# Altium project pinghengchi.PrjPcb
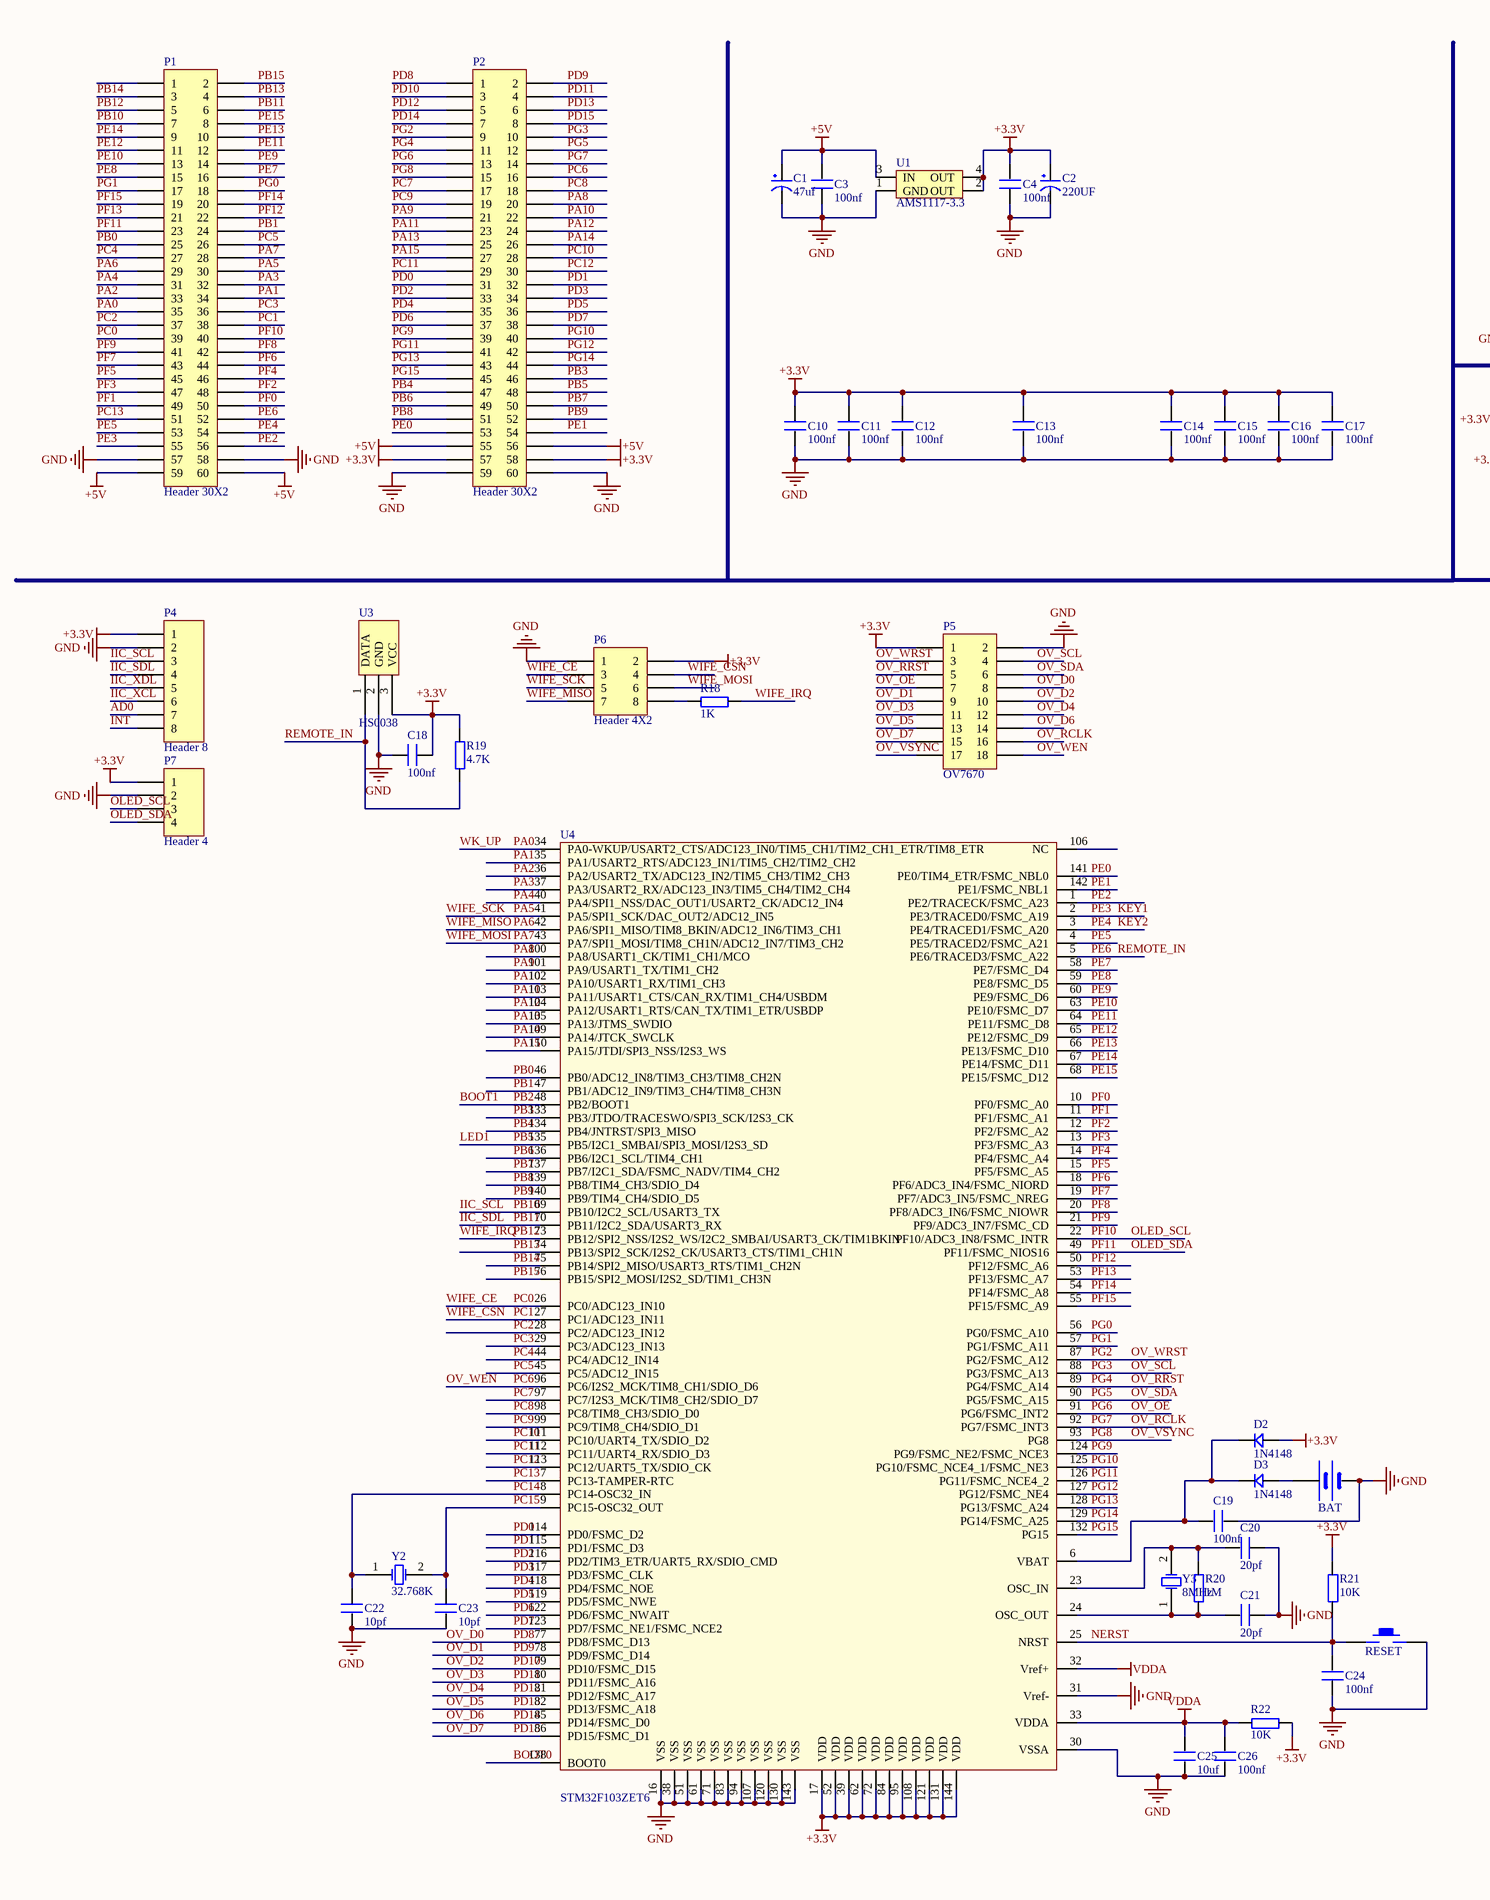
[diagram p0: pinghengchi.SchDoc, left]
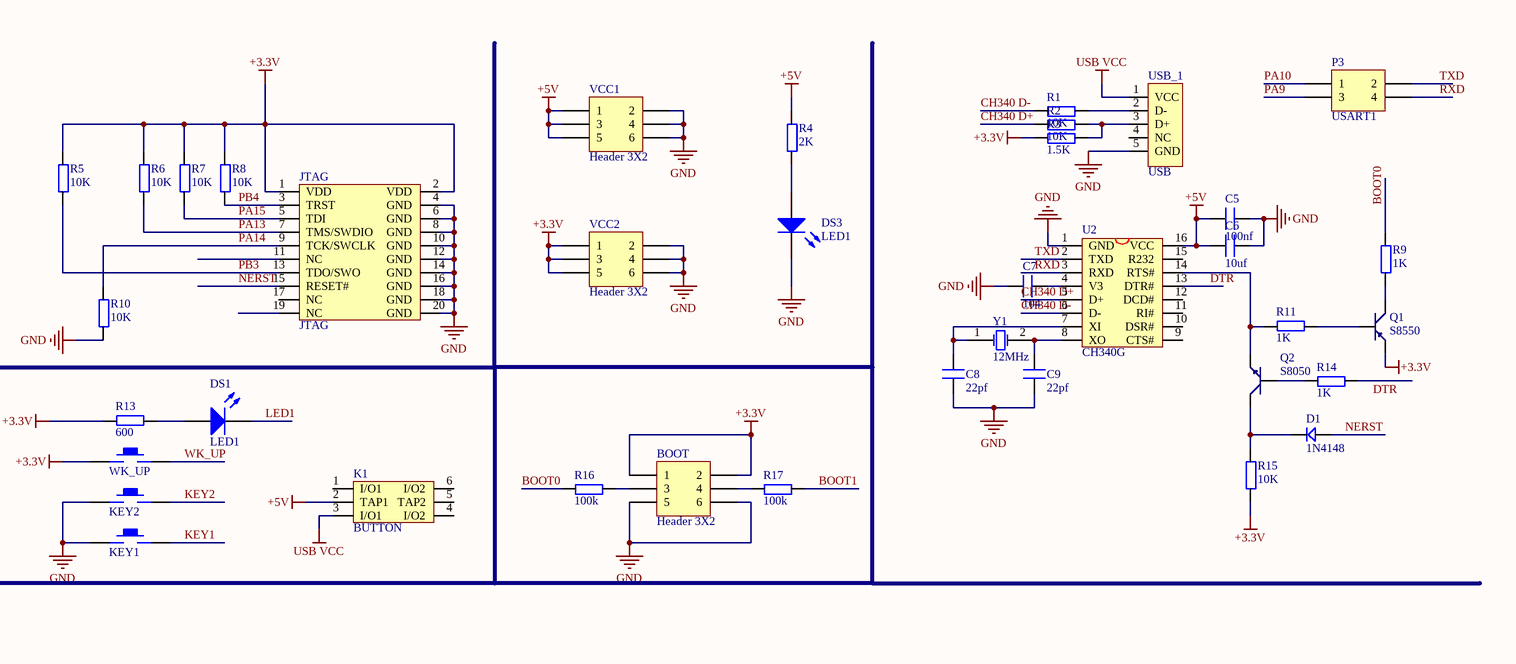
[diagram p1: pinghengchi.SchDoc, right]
1 sheet, 79 parts. Net scope: global (net labels, ports and power ports of the same name join across sheets).
Board file: pinghengchi.PcbDoc

## Sheet pinghengchi.SchDoc
size A2

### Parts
BAT  BATT  [BATM]  (value not drawn)
BOOT  Header 3X2  [HDR2X3]
C1  47uf  [CC6.56.5]
C2  220UF  [CC6.56.5]
C3  100nf  [0603P]
C4  100nf  [0603P]
C5  100nf  [0603P]
C6  10uf  [0603P]
C7  104  [0603P]
C8  22pf  [0603P]
C9  22pf  [0603P]
C10  100nf  [0603P]
C11  100nf  [0603P]
C12  100nf  [0603P]
C13  100nf  [0603P]
C14  100nf  [0603P]
C15  100nf  [0603P]
C16  100nf  [0603P]
C17  100nf  [0603P]
C18  100nf  [0603P]
C19  100nf  [0603P]
C20  20pf  [0603P]
C21  20pf  [0603P]
C22  10pf  [0603P]
C23  10pf  [0603P]
C24  100nf  [0603P]
C25  10uf  [0603P]
C26  100nf  [0603P]
D1  1N4148  [DIODE_SOP]
D2  1N4148  [DIODE_SOP]
D3  1N4148  [DIODE_SOP]
DS1  LED1  [SMDLED]
DS3  LED1  [SMDLED]
JTAG  JTAG  [JTAG_20]
K1  BUTTON  [BTN8.5*8.5]
KEY1  KEY_M  [KEY_M]  (value not drawn)
KEY2  KEY_M  [KEY_M]  (value not drawn)
P1  Header 30X2  [HDR2X30]
P2  Header 30X2  [HDR2X30]
P3  USART1  [HDR2X2]
P4  Header 8  [HDR1X8]
P5  OV7670  [HDR2X9]
P6  Header 4X2  [HDR2X4]
P7  Header 4  [HDR1X4]
Q1  S8550  [SOT-23R]
Q2  S8050  [SOT-23R]
R1  10K  [0603P]
R2  10K  [0603P]
R3  1.5K  [0603P]
R4  2K  [0603P]
R5  10K  [0603P]
R6  10K  [0603P]
R7  10K  [0603P]
R8  10K  [0603P]
R9  1K  [0603P]
R10  10K  [0603P]
R11  1K  [0603P]
R13  600  [0603P]
R14  1K  [0603P]
R15  10K  [0603P]
R16  100k  [0603P]
R17  100k  [0603P]
R18  1K  [0603P]
R19  4.7K  [0603P]
R20  1M  [0603P]
R21  10K  [0603P]
R22  10K  [0603P]
RESET  KEY_M  [KEY_M]  (value not drawn)
U1  AMS1117-3.3  [AMS1117]
U2  CH340G  [SOP16M]
U3  HS0038  [HS0038]
U4  STM32F103ZET6  [LQFP144]
USB_1  USB  [USB/SM0.8-6H5]
VCC1  Header 3X2  [HDR2X3]
VCC2  Header 3X2  [HDR2X3]
WK_UP  KEY_M  [KEY_M]  (value not drawn)
Y1  12MHz  [XTAL_US]
Y2  32.768K  [XTAL_US]
Y3  8MHz  [XTAL_US]

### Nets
+3.3V: BOOT.1 BOOT.2 C2.1(VCC) C4.2 C10.2 C11.2 C12.2 C13.2 C14.2 C15.2 C16.2 C17.2 C18.2 D2.1 JTAG.1(VDD) JTAG.2(VDD) P2.57 P2.58 P4.1 P5.1 P6.2 P7.1 Q1.1(E) R3.1 R5.2 R6.2 R7.2 R8.2 R13.2 R15.1 R19.2 R21.2 R22.2 U1.2(OUT) U1.4(OUT) U3.3(VCC) U4.17(VDD) U4.39(VDD) U4.52(VDD) U4.62(VDD) U4.72(VDD) U4.84(VDD) U4.95(VDD) U4.108(VDD) U4.121(VDD) U4.131(VDD) U4.144(VDD) VCC2.1 VCC2.3 VCC2.5 WK_UP.1
+5V: C1.1(VCC) C3.2 C5.1 C6.1 K1.2(TAP1) P1.59 P1.60 P2.55 P2.56 R4.2 U1.3(IN) U2.16(VCC) VCC1.1 VCC1.3 VCC1.5
GND: BAT.2(GND) BOOT.5 BOOT.6 C1.2(GND) C2.2(GND) C3.1 C4.1 C5.2 C6.2 C7.1 C8.1 C9.1 C10.1 C11.1 C12.1 C13.1 C14.1 C15.1 C16.1 C17.1 C18.1 C19.2 C20.1 C21.1 C22.1 C23.1 C24.1 C25.1 C26.1 DS3.2(K) JTAG.4(GND) JTAG.6(GND) JTAG.8(GND) JTAG.10(GND) JTAG.12(GND) JTAG.14(GND) JTAG.16(GND) JTAG.18(GND) JTAG.20(GND) KEY1.1 KEY2.1 P1.57 P1.58 P2.59 P2.60 P4.2 P5.2 P6.1 P7.2 R10.1 RESET.2 U1.1(GND) U2.1(GND) U3.2(GND) U4.16(VSS) U4.30(VSSA) U4.31(Vref-) U4.38(VSS) U4.51(VSS) U4.61(VSS) U4.71(VSS) U4.83(VSS) U4.94(VSS) U4.107(VSS) U4.120(VSS) U4.130(VSS) U4.143(VSS) USB_1.5(GND) VCC1.2 VCC1.4 VCC1.6 VCC2.2 VCC2.4 VCC2.6
USB VCC: K1.3(I/O1) USB_1.1(VCC)
VDDA: C25.2 C26.2 R22.1 U4.32(Vref+) U4.33(VDDA)
AD0: P4.7
BOOT0: R9.2 R16.1 U4.138(BOOT0)
BOOT1: R17.2 U4.48(PB2/BOOT1)  [also labelled PB2]
CH340 D+: R2.1 U2.5(D+)
CH340 D-: R1.1 U2.6(D-)
DTR: R14.2 U2.13(DTR#)
IIC_SCL: P1.7 P4.3 U4.69(PB10/I2C2_SCL/USART3_TX)  [also labelled PB10]
IIC_SDL: P1.6 P4.4 U4.70(PB11/I2C2_SDA/USART3_RX)  [also labelled PB11]
IIC_XCL: P4.6
IIC_XDL: P4.5
INT: P4.8
KEY1: KEY1.2 P1.55 U4.2(PE3/TRACED0/FSMC_A19)  [also labelled PE3]
KEY2: KEY2.2 P1.54 U4.3(PE4/TRACED1/FSMC_A20)  [also labelled PE4]
LED1: DS1.2(K) P2.48 U4.135(PB5/I2C1_SMBAI/SPI3_MOSI/I2S3_SD)  [also labelled PB5]
NERST: C24.2 D1.1 JTAG.15(RESET#) R21.1 RESET.1 U4.25(NRST)
OLED_SCL: P1.40 P7.3 U4.22(PF10/ADC3_IN8/FSMC_INTR)  [also labelled PF10]
OLED_SDA: P1.23 P7.4 U4.49(PF11/FSMC_NIOS16)  [also labelled PF11]
OV_D0: P2.1 P5.8 U4.77(PD8/FSMC_D13)  [also labelled PD8]
OV_D1: P2.2 P5.9 U4.78(PD9/FSMC_D14)  [also labelled PD9]
OV_D2: P2.3 P5.10 U4.79(PD10/FSMC_D15)  [also labelled PD10]
OV_D3: P2.4 P5.11 U4.80(PD11/FSMC_A16)  [also labelled PD11]
OV_D4: P2.5 P5.12 U4.81(PD12/FSMC_A17)  [also labelled PD12]
OV_D5: P2.6 P5.13 U4.82(PD13/FSMC_A18)  [also labelled PD13]
OV_D6: P2.7 P5.14 U4.85(PD14/FSMC_D0)  [also labelled PD14]
OV_D7: P2.8 P5.15 U4.86(PD15/FSMC_D1)  [also labelled PD15]
OV_OE: P2.13 P5.7 U4.91(PG6/FSMC_INT2)  [also labelled PG6]
OV_RCLK: P2.14 P5.16 U4.92(PG7/FSMC_INT3)  [also labelled PG7]
OV_RRST: P2.11 P5.5 U4.89(PG4/FSMC_A14)  [also labelled PG4]
OV_SCL: P2.10 P5.4 U4.88(PG3/FSMC_A13)  [also labelled PG3]
OV_SDA: P2.12 P5.6 U4.90(PG5/FSMC_A15)  [also labelled PG5]
OV_VSYNC: P2.15 P5.17 U4.93(PG8)  [also labelled PG8]
OV_WEN: P2.16 P5.18 U4.96(PC6/I2S2_MCK/TIM8_CH1/SDIO_D6)  [also labelled PC6]
OV_WRST: P2.9 P5.3 U4.87(PG2/FSMC_A12)  [also labelled PG2]
PA0: P1.35 U4.34(PA0-WKUP/USART2_CTS/ADC123_IN0/TIM5_CH1/TIM2_CH1_ETR/TIM8_ETR) WK_UP.2  [also labelled WK_UP]
PA1: P1.34 U4.35(PA1/USART2_RTS/ADC123_IN1/TIM5_CH2/TIM2_CH2)
PA2: P1.33 U4.36(PA2/USART2_TX/ADC123_IN2/TIM5_CH3/TIM2_CH3)
PA3: P1.32 U4.37(PA3/USART2_RX/ADC123_IN3/TIM5_CH4/TIM2_CH4)
PA4: P1.31 U4.40(PA4/SPI1_NSS/DAC_OUT1/USART2_CK/ADC12_IN4)
PA5: P1.30 P6.5 U4.41(PA5/SPI1_SCK/DAC_OUT2/ADC12_IN5)  [also labelled WIFE_SCK]
PA6: P1.29 P6.7 U4.42(PA6/SPI1_MISO/TIM8_BKIN/ADC12_IN6/TIM3_CH1)  [also labelled WIFE_MISO]
PA7: P1.28 P6.6 U4.43(PA7/SPI1_MOSI/TIM8_CH1N/ADC12_IN7/TIM3_CH2)  [also labelled WIFE_MOSI]
PA8: P2.20 U4.100(PA8/USART1_CK/TIM1_CH1/MCO)
PA9: P2.21 P3.3 U4.101(PA9/USART1_TX/TIM1_CH2)
PA10: P2.22 P3.1 U4.102(PA10/USART1_RX/TIM1_CH3)
PA11: P2.23 U4.103(PA11/USART1_CTS/CAN_RX/TIM1_CH4/USBDM)
PA12: P2.24 U4.104(PA12/USART1_RTS/CAN_TX/TIM1_ETR/USBDP)
PA13: JTAG.7(TMS/SWDIO) P2.25 R6.1 U4.105(PA13/JTMS_SWDIO)
PA14: JTAG.9(TCK/SWCLK) P2.26 R10.2 U4.109(PA14/JTCK_SWCLK)
PA15: JTAG.5(TDI) P2.27 R7.1 U4.110(PA15/JTDI/SPI3_NSS/I2S3_WS)
PB0: P1.25 U4.46(PB0/ADC12_IN8/TIM3_CH3/TIM8_CH2N)
PB1: P1.24 U4.47(PB1/ADC12_IN9/TIM3_CH4/TIM8_CH3N)
PB3: JTAG.13(TDO/SWO) P2.46 R5.1 U4.133(PB3/JTDO/TRACESWO/SPI3_SCK/I2S3_CK)
PB4: JTAG.3(TRST) P2.47 R8.1 U4.134(PB4/JNTRST/SPI3_MISO)
PB6: P2.49 U4.136(PB6/I2C1_SCL/TIM4_CH1)
PB7: P2.50 U4.137(PB7/I2C1_SDA/FSMC_NADV/TIM4_CH2)
PB8: P2.51 U4.139(PB8/TIM4_CH3/SDIO_D4)
PB9: P2.52 U4.140(PB9/TIM4_CH4/SDIO_D5)
PB12: P1.5 R18.2 U4.73(PB12/SPI2_NSS/I2S2_WS/I2C2_SMBAI/USART3_CK/TIM1BKIN)  [also labelled WIFE_IRQ]
PB13: P1.4 U4.74(PB13/SPI2_SCK/I2S2_CK/USART3_CTS/TIM1_CH1N)
PB14: P1.3 U4.75(PB14/SPI2_MISO/USART3_RTS/TIM1_CH2N)
PB15: P1.2 U4.76(PB15/SPI2_MOSI/I2S2_SD/TIM1_CH3N)
PC0: P1.39 P6.3 U4.26(PC0/ADC123_IN10)  [also labelled WIFE_CE]
PC1: P1.38 P6.4 U4.27(PC1/ADC123_IN11)  [also labelled WIFE_CSN]
PC2: P1.37 U4.28(PC2/ADC123_IN12)
PC3: P1.36 U4.29(PC3/ADC123_IN13)
PC4: P1.27 U4.44(PC4/ADC12_IN14)
PC5: P1.26 U4.45(PC5/ADC12_IN15)
PC7: P2.17 U4.97(PC7/I2S3_MCK/TIM8_CH2/SDIO_D7)
PC8: P2.18 U4.98(PC8/TIM8_CH3/SDIO_D0)
PC9: P2.19 U4.99(PC9/TIM8_CH4/SDIO_D1)
PC10: P2.28 U4.111(PC10/UART4_TX/SDIO_D2)
PC11: P2.29 U4.112(PC11/UART4_RX/SDIO_D3)
PC12: P2.30 U4.113(PC12/UART5_TX/SDIO_CK)
PC13: P1.51 U4.7(PC13-TAMPER-RTC)
PC14: C22.2 U4.8(PC14-OSC32_IN) Y2.1(OSC1)
PC15: C23.2 U4.9(PC15-OSC32_OUT) Y2.2(OSC2)
PD0: P2.31 U4.114(PD0/FSMC_D2)
PD1: P2.32 U4.115(PD1/FSMC_D3)
PD2: P2.33 U4.116(PD2/TIM3_ETR/UART5_RX/SDIO_CMD)
PD3: P2.34 U4.117(PD3/FSMC_CLK)
PD4: P2.35 U4.118(PD4/FSMC_NOE)
PD5: P2.36 U4.119(PD5/FSMC_NWE)
PD6: P2.37 U4.122(PD6/FSMC_NWAIT)
PD7: P2.38 U4.123(PD7/FSMC_NE1/FSMC_NCE2)
PE0: P2.53 U4.141(PE0/TIM4_ETR/FSMC_NBL0)
PE1: P2.54 U4.142(PE1/FSMC_NBL1)
PE2: P1.56 U4.1(PE2/TRACECK/FSMC_A23)
PE5: P1.53 U4.4(PE5/TRACED2/FSMC_A21)
PE6: P1.52 R19.1 U3.1(DATA) U4.5(PE6/TRACED3/FSMC_A22)  [also labelled REMOTE_IN]
PE7: P1.16 U4.58(PE7/FSMC_D4)
PE8: P1.15 U4.59(PE8/FSMC_D5)
PE9: P1.14 U4.60(PE9/FSMC_D6)
PE10: P1.13 U4.63(PE10/FSMC_D7)
PE11: P1.12 U4.64(PE11/FSMC_D8)
PE12: P1.11 U4.65(PE12/FSMC_D9)
PE13: P1.10 U4.66(PE13/FSMC_D10)
PE14: P1.9 U4.67(PE14/FSMC_D11)
PE15: P1.8 U4.68(PE15/FSMC_D12)
PF0: P1.50 U4.10(PF0/FSMC_A0)
PF1: P1.49 U4.11(PF1/FSMC_A1)
PF2: P1.48 U4.12(PF2/FSMC_A2)
PF3: P1.47 U4.13(PF3/FSMC_A3)
PF4: P1.46 U4.14(PF4/FSMC_A4)
PF5: P1.45 U4.15(PF5/FSMC_A5)
PF6: P1.44 U4.18(PF6/ADC3_IN4/FSMC_NIORD)
PF7: P1.43 U4.19(PF7/ADC3_IN5/FSMC_NREG)
PF8: P1.42 U4.20(PF8/ADC3_IN6/FSMC_NIOWR)
PF9: P1.41 U4.21(PF9/ADC3_IN7/FSMC_CD)
PF12: P1.22 U4.50(PF12/FSMC_A6)
PF13: P1.21 U4.53(PF13/FSMC_A7)
PF14: P1.20 U4.54(PF14/FSMC_A8)
PF15: P1.19 U4.55(PF15/FSMC_A9)
PG0: P1.18 U4.56(PG0/FSMC_A10)
PG1: P1.17 U4.57(PG1/FSMC_A11)
PG9: P2.39 U4.124(PG9/FSMC_NE2/FSMC_NCE3)
PG10: P2.40 U4.125(PG10/FSMC_NCE4_1/FSMC_NE3)
PG11: P2.41 U4.126(PG11/FSMC_NCE4_2)
PG12: P2.42 U4.127(PG12/FSMC_NE4)
PG13: P2.43 U4.128(PG13/FSMC_A24)
PG14: P2.44 U4.129(PG14/FSMC_A25)
PG15: P2.45 U4.132(PG15)
RXD: P3.4 U2.3(RXD)
TXD: P3.2 U2.2(TXD)
NetBAT_1: BAT.1(VCC) D3.1
NetBOOT_3: BOOT.3 R16.2
NetBOOT_4: BOOT.4 R17.1
NetC7_2: C7.2 U2.4(V3)
NetC8_2: C8.2 U2.7(XI) Y1.1(OSC1)
NetC9_2: C9.2 U2.8(XO) Y1.2(OSC2)
NetC19_1: C19.1 D2.2 D3.2 U4.6(VBAT)
NetC20_2: C20.2 R20.2 U4.23(OSC_IN) Y3.2(OSC2)
NetC21_2: C21.2 R20.1 U4.24(OSC_OUT) Y3.1(OSC1)
NetD1_2: D1.2 Q2.3(C) R15.2
NetDS1_1: DS1.1(A) R13.1
NetDS3_1: DS3.1(A) R4.1
NetP6_8: P6.8 R18.1
NetQ1_2: Q1.2(B) R11.1
NetQ1_3: Q1.3(C) R9.1
NetQ2_1: Q2.1(E) R11.2 U2.14(RTS#)
NetQ2_2: Q2.2(B) R14.1
NetR1_2: R1.2 USB_1.2(D-)
NetR2_2: R2.2 R3.2 USB_1.3(D+)

Not connected (* = marked no-connect by the designer): JTAG 11(NC) 17(NC) 19(NC); K1 1(I/O1) 4(I/O2) 5(TAP2) 6(I/O2); P1 1; U2 9(CTS#) 10(DSR#) 11(RI#) 12(DCD#) 15(R232); U4 106(NC); USB_1 4(NC)

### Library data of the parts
BAT = BAT
BOOT VCC1 VCC2 = Header 3X2: Header, 3-Pin, Dual row
C1 C2 = CAP
C3-C26 = C
D1-D3 = D
DS1 DS3 = LED2: Typical RED, GREEN, YELLOW, AMBER GaAs LED
P1 P2 = Header 30X2: Header, 30-Pin, Dual row
P3 = Header 2X2: Header, 2-Pin, Dual row
P4 = Header 8: Header, 8-Pin
P5 = Header 9X2: Header, 9-Pin, Dual row
P6 = Header 4X2: Header, 4-Pin, Dual row
P7 = Header 4: Header, 4-Pin
Q1 = PNP: 8550/BCW68
Q2 = NPN: 8050/BCW846/BCW847
R1-R11 R13-R22 = R
U1 = AMS1117
U2 = CH340G: USB2UART
USB_1 = USB5
Y1-Y3 = XTAL: Crystal Oscillator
